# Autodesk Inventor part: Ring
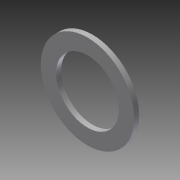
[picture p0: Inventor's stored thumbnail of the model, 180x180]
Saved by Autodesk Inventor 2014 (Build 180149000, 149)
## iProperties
Created: 2009-03
Part Number: Ring
Document SubType Name: Modeling
Designer: tangg
Density: 7.86 g/cm^3
Material: Steel, Mild
Mass: 47.3376 g
Surface Area: 38.1795 cm^2
Volume: 6.02259 cm^3
Appearance: Steel
Author: tangg
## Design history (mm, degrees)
sketch "Sketch1"
  geometry: C1 r 18.78 at (-13.18, 0); C2 r 28 at (-13.18, 0) reference; C3 r 28 at (-13.18, 0) reference; C4 r 28.005 at (-13.18, 0); 1 further point
  constraints: 2 centre point, 1 coincident
  dimensions: "d3" = 0.005 radial gap between concentric circles of C2 C4
extrude "Extrusion1" new body sketch "Sketch1" distance "d0" = 3; taper "d1" = 0 deg
body "Solid1"
node "Reference2"
node "Reference3"
